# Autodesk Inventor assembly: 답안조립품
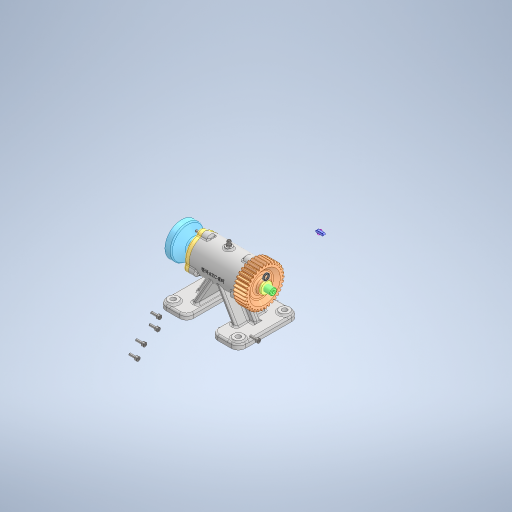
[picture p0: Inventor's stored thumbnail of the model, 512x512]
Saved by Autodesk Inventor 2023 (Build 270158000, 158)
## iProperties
Created: 2026-04
Part Number: 답안조립품
Document SubType Name: Assembly
Designer: home
Author: home
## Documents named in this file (16)
- C:\Users\home\Desktop\760403V1014\답안조립품.iam
- C:\Users\home\Desktop\760403V1014\본체.ipt
- C:\Users\home\Desktop\760403V1014\6각 구멍붙이 볼트 M4x12.ipt
- C:\Users\home\Desktop\760403V1014\그리스 니플 M6x0,75.ipt
- C:\Users\home\Desktop\760403V1014\깊은 홈 볼 베어링 6004.ipt
- C:\Users\home\Desktop\760403V1014\스퍼 기어.ipt
- C:\Users\home\Desktop\760403V1014\스프링 와셔 M4.ipt
- C:\Users\home\Desktop\760403V1014\실링.ipt
- C:\Users\home\Desktop\760403V1014\엔드 캡.ipt
- C:\Users\home\Desktop\760403V1014\오일 실 20 35 8.ipt
- C:\Users\home\Desktop\760403V1014\축.ipt
- C:\Users\home\Desktop\760403V1014\커버.ipt
- C:\Users\home\Desktop\760403V1014\평 와셔 M4.ipt
- C:\Users\home\Desktop\760403V1014\평행 키 4x4x14.ipt
- C:\Users\home\Desktop\760403V1014\플랜지.ipt
- C:\Users\home\Desktop\760403V1014\플러그 M6x0,75.ipt
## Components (12 placed, 4 different names)
1. 6각 구멍붙이 볼트 M4x12:1
2. 그리스 니플 M6x0,75:1
3. 플랜지:1
4. 플러그 M6x0,75:1
5. 6각 구멍붙이 볼트 M4x12:2
6. 6각 구멍붙이 볼트 M4x12:3
7. 6각 구멍붙이 볼트 M4x12:4
8. 6각 구멍붙이 볼트 M4x12:5
9. 6각 구멍붙이 볼트 M4x12:6
10. 6각 구멍붙이 볼트 M4x12:7
11. 6각 구멍붙이 볼트 M4x12:8
12. 6각 구멍붙이 볼트 M4x12:9
